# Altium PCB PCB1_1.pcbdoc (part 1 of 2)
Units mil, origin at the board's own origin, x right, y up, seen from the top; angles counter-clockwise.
Board outline 2576.88 x 4443.16 mil, 6 copper layers (Top Layer, Inner1, Inner2, Inner3, Inner4, Bottom Layer); 86 components, 97 nets, 400 pads, 188 vias.
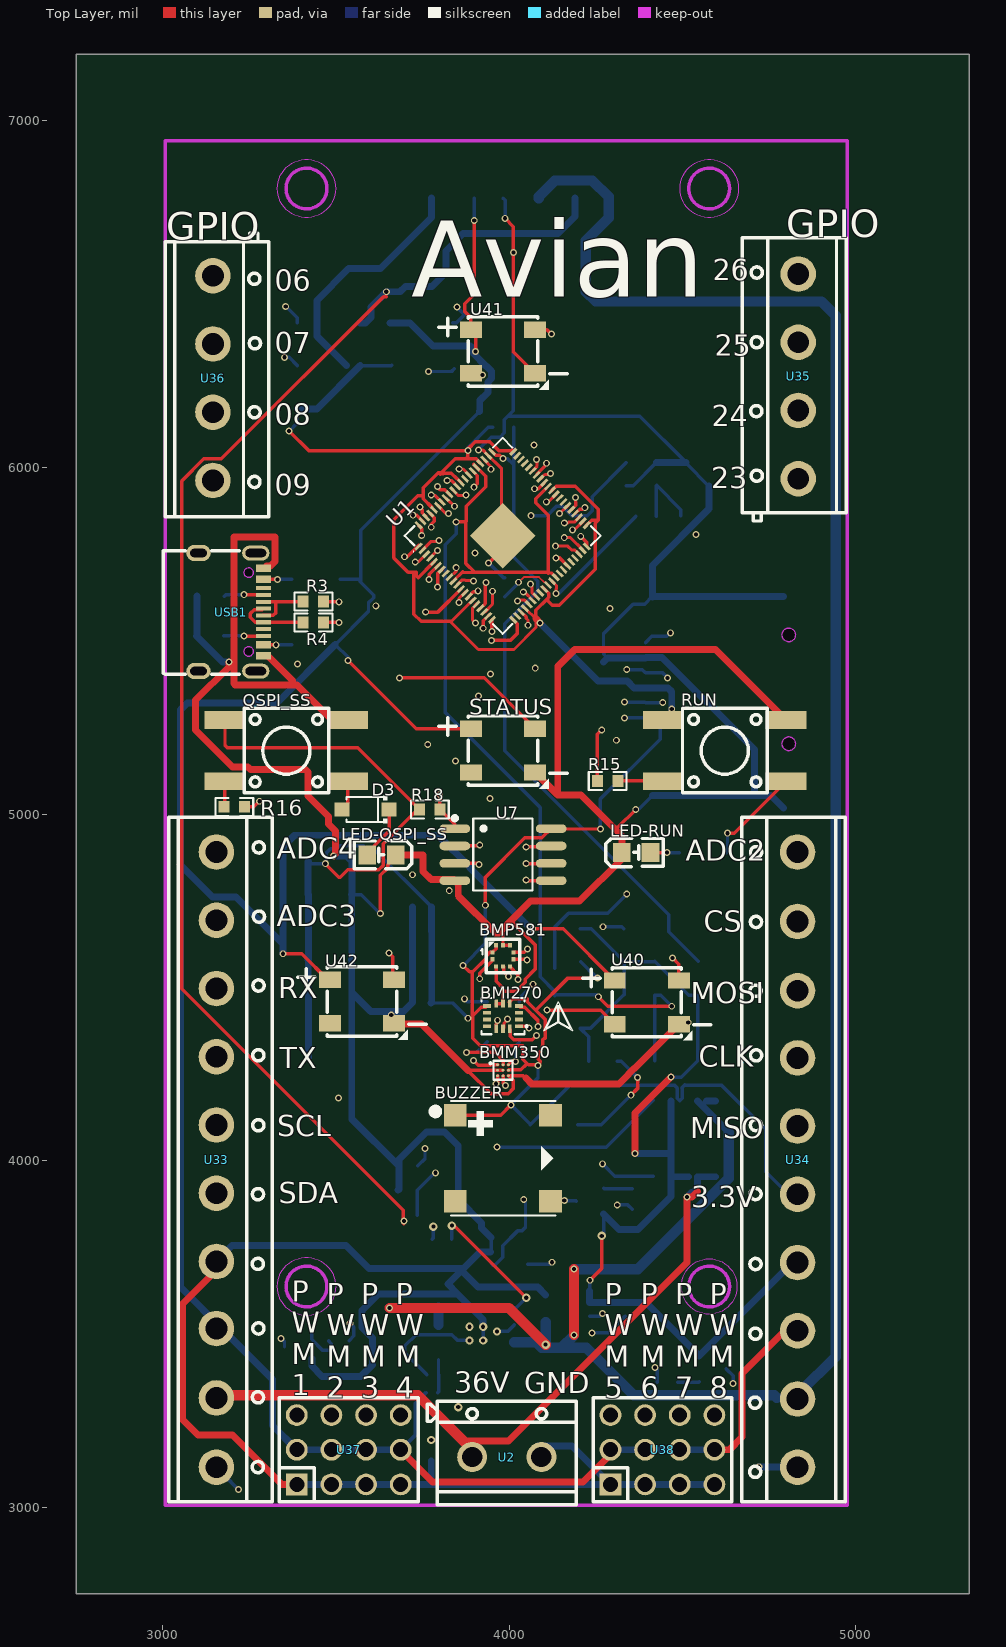
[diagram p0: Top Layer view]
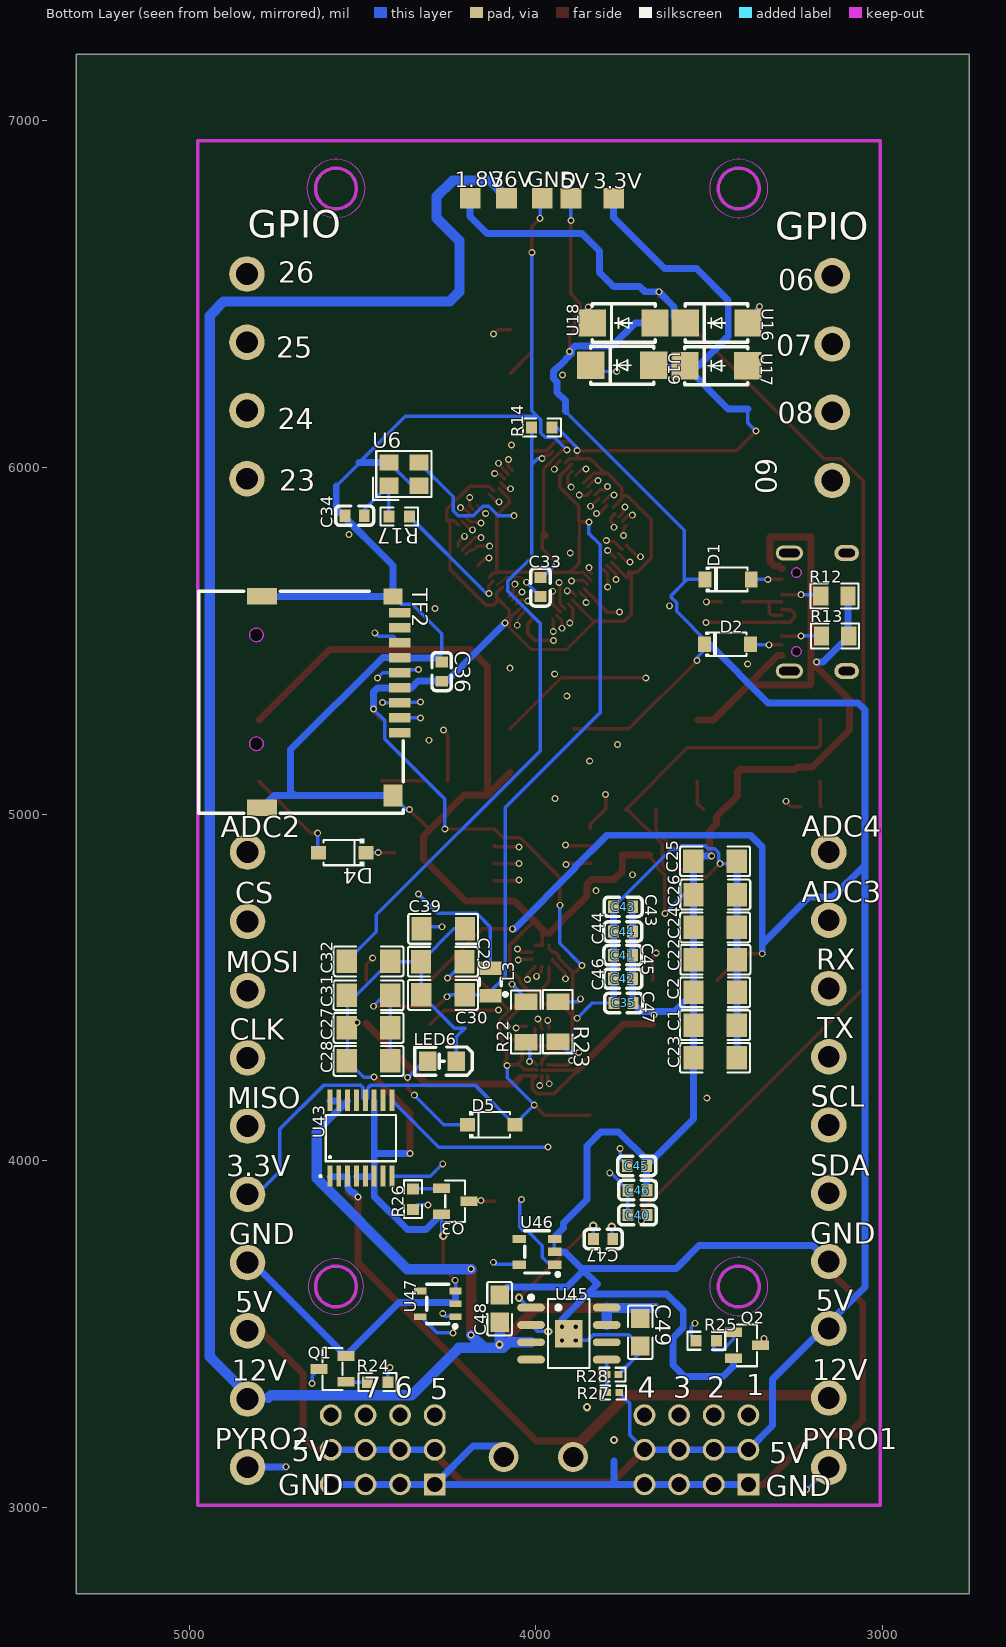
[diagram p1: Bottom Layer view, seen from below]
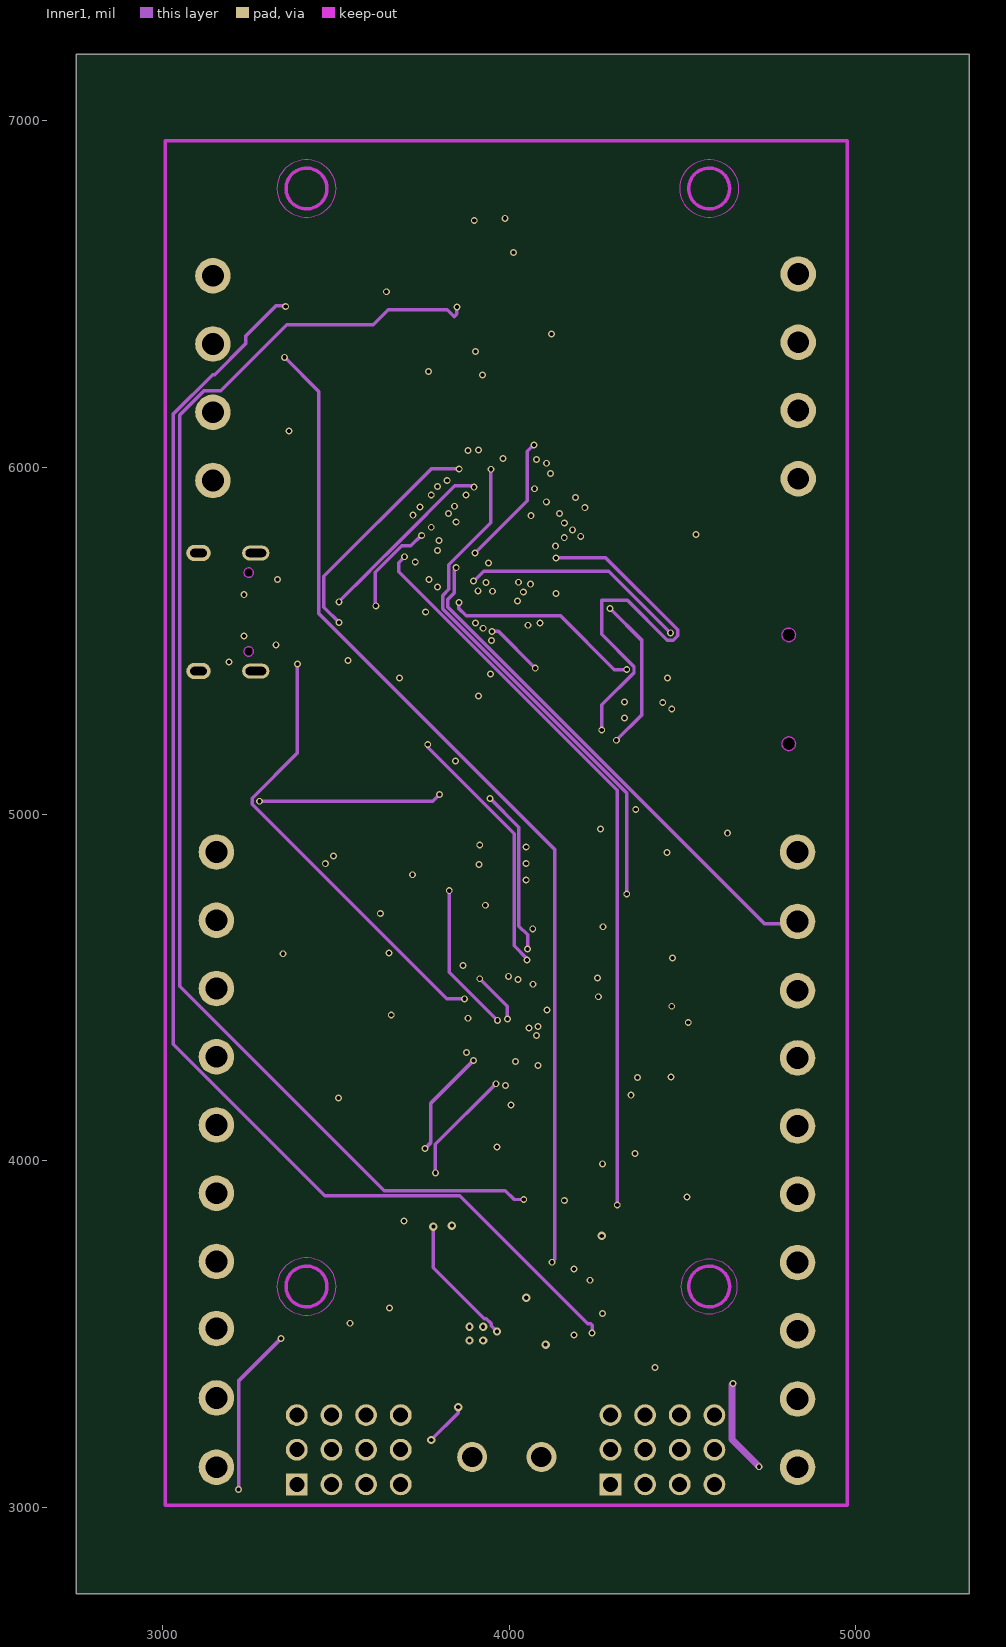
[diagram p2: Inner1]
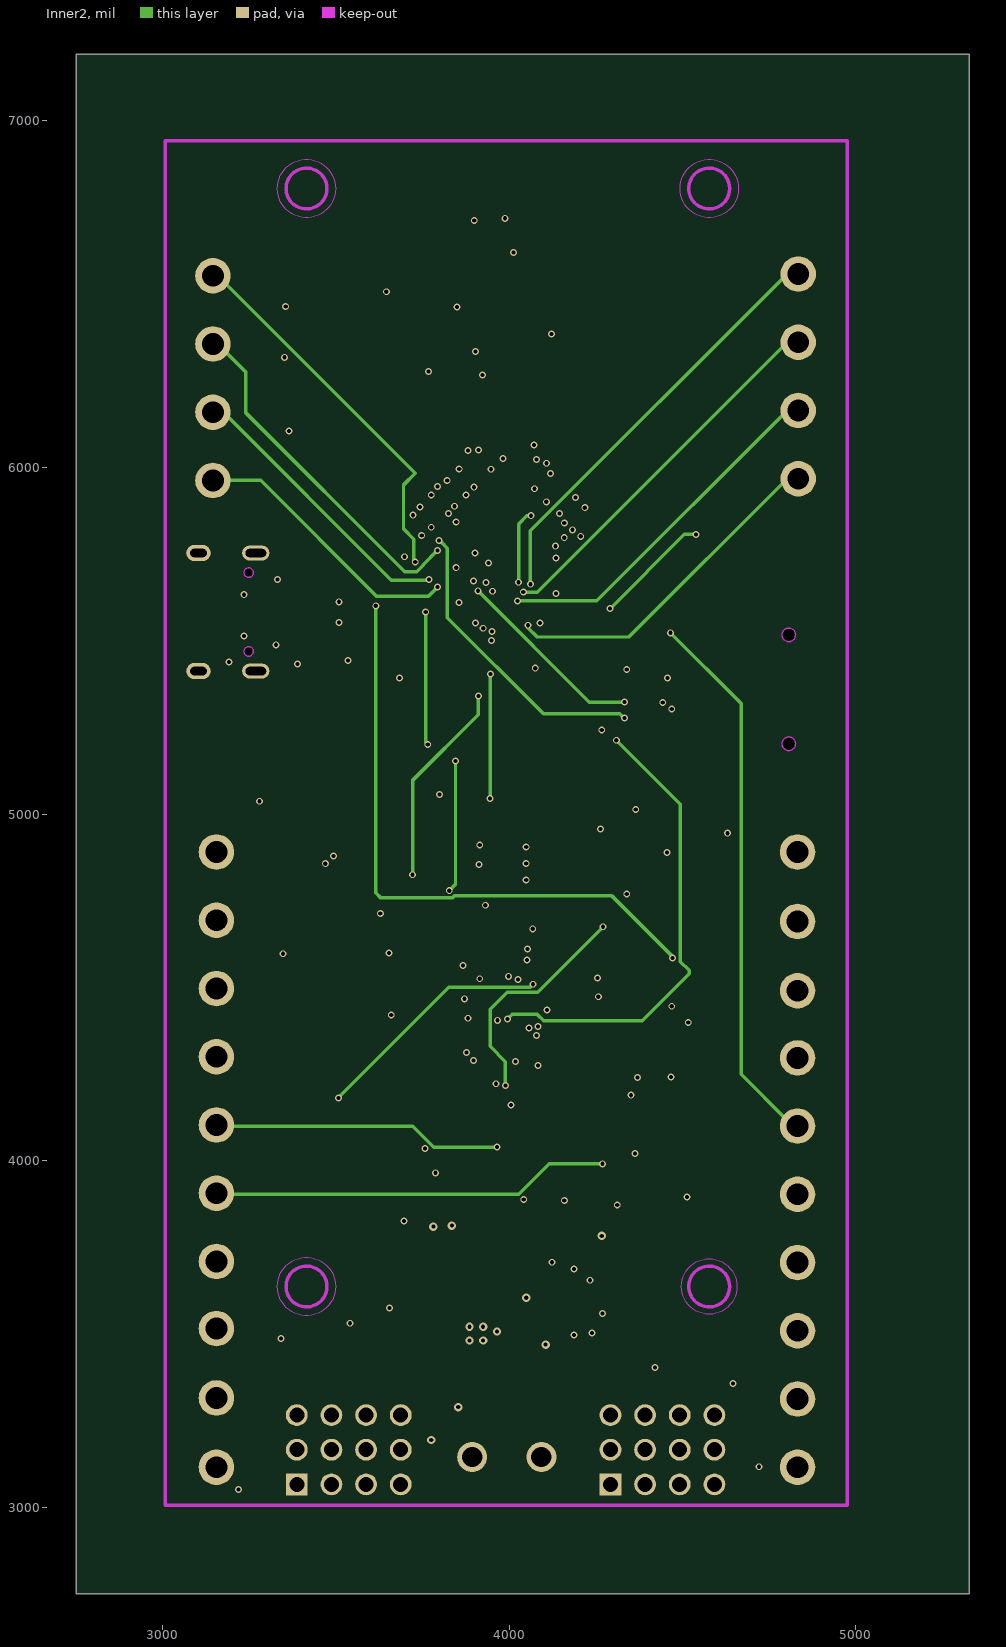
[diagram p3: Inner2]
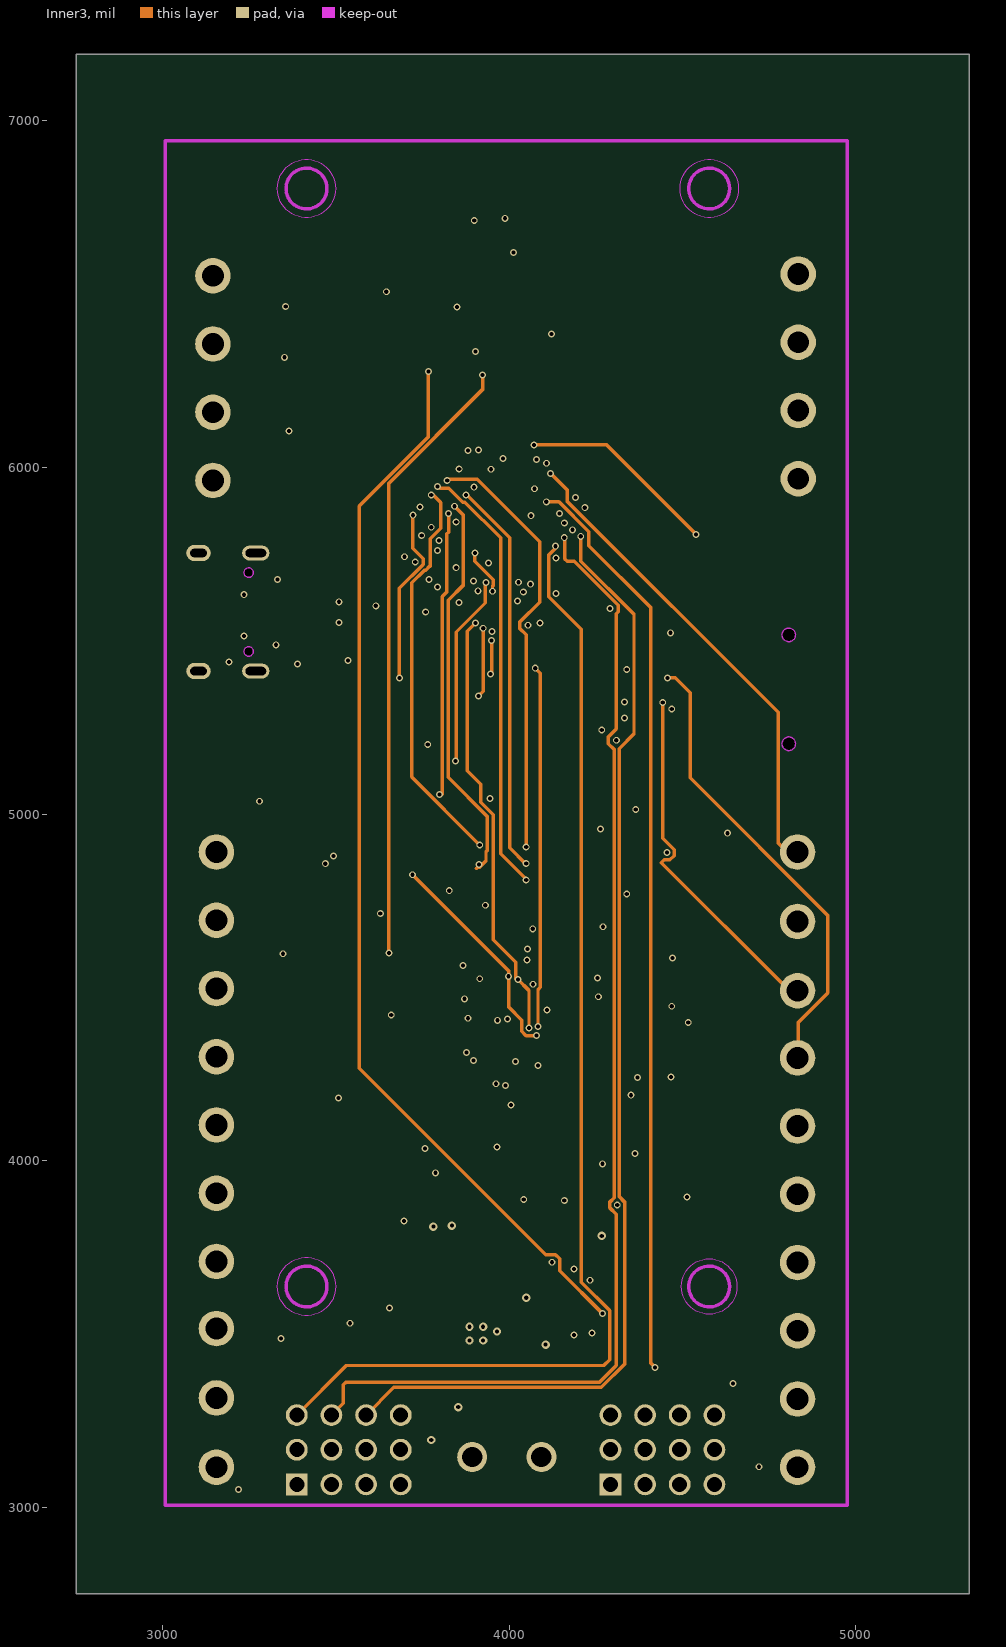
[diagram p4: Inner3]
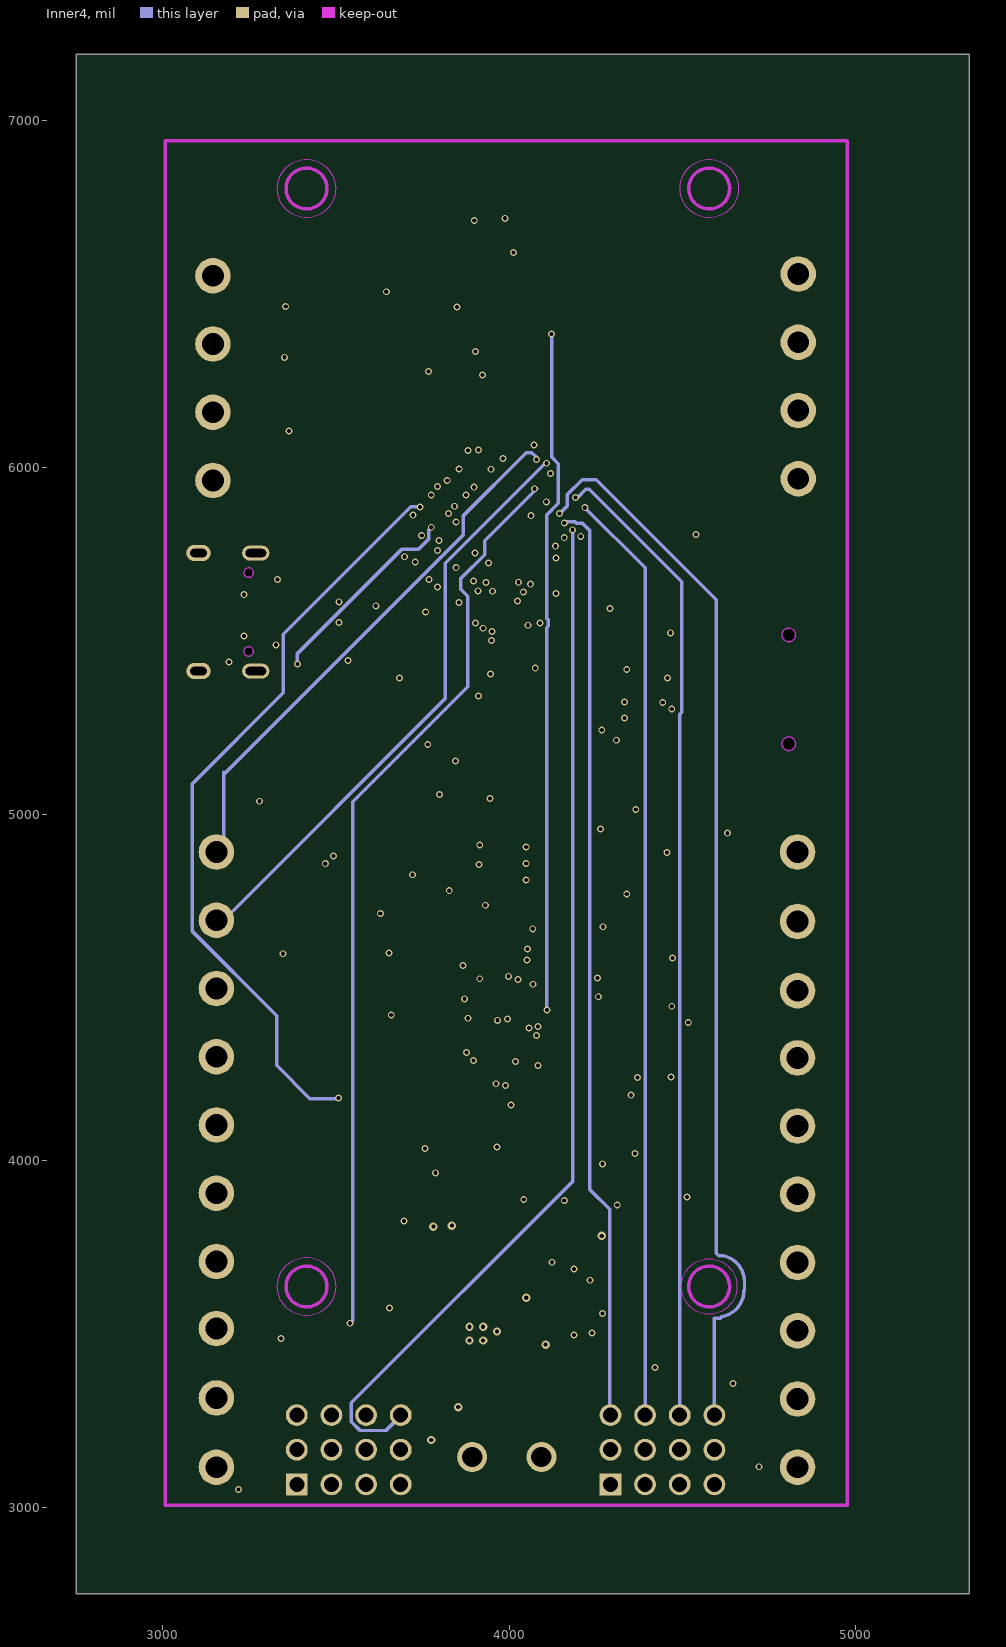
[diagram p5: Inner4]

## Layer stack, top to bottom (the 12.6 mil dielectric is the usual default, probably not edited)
Top Layer: signal copper (thickness not stored)
Dielectric: dielectric 12.6, FR-4, Dk 4.8
Inner1: signal copper (thickness not stored)
Dielectric: dielectric 12.6, FR-4, Dk 4.8
Inner2: signal copper (thickness not stored)
Dielectric: dielectric 12.6, FR-4, Dk 4.8
Inner3: signal copper (thickness not stored)
Dielectric: dielectric 12.6, FR-4, Dk 4.8
Inner4: signal copper (thickness not stored)
Dielectric: dielectric 12.6, FR-4, Dk 4.8
Bottom Layer: signal copper (thickness not stored)

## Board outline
5326.88,2750 2750,2750 2750,7193.16 5326.88,7193.16

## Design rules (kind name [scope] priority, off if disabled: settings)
BoardOutlineClearance copperThickness1oz [All] p0: genericclearance=10 ignorepadtopadclearanceinfootprint=FALSE except(0: Arc-SplitContinuation Track-SplitContinuation SMDPad-SplitContinuation THPad-SplitContinuation Via-SplitContinuation Fill-SplitContinuation Poly-SplitContinuation Region-SplitContinuation Text-SplitContinuation; 6: Track-CutoutEdge SMDPad-CutoutEdge THPad-CutoutEdge Via-CutoutEdge Region-CutoutEdge; 11.8: Track-OutlineEdge SMDPad-OutlineEdge THPad-OutlineEdge Via-OutlineEdge Fill-OutlineEdge Region-OutlineEdge Poly-OutlineEdge Text-OutlineEdge Fill-CutoutEdge)
BoardOutlineClearance copperThickness2oz [All] p0: genericclearance=10 ignorepadtopadclearanceinfootprint=FALSE except(0: Arc-SplitContinuation Track-SplitContinuation SMDPad-SplitContinuation THPad-SplitContinuation Via-SplitContinuation Fill-SplitContinuation Poly-SplitContinuation Region-SplitContinuation Text-SplitContinuation; 6: Track-CutoutEdge SMDPad-CutoutEdge THPad-CutoutEdge Via-CutoutEdge Region-CutoutEdge; 11.8: Track-OutlineEdge SMDPad-OutlineEdge THPad-OutlineEdge Via-OutlineEdge Fill-OutlineEdge Region-OutlineEdge Poly-OutlineEdge Text-OutlineEdge Fill-CutoutEdge)
Clearance copperThickness1oz [(InNet('GND') OR InNet('+5V') OR InNet('RPD-') OR InNet('RPD+') OR InNet('3.3V') OR InNet('1.1V') OR InNet('1.8V') OR InNet('XIN') OR InNet('QSPI_SS') OR InNet('XOUT') OR InNet('QSPI_SD3') OR InNet('QSPI_SCLK') OR InNet('QSPI_SDO') OR InNet('QSPI_SD2') OR InNet('QSPI_SD1') OR InNet('SDCS') OR InNet('MISO') OR InNet('CLK') OR InNet('MOSI') OR InNet('$5N1577') OR InNet('$5N4916') OR InNet('$5N4199') OR InNet('$5N4153') OR InNet('$5N4367') OR InNet('$5N1500') OR InNet('$5N714') OR InNet('$5N753') OR InNet('$5N865') OR InNet('$5N3555') OR InNet('$3N4271') OR InNet('$3N4443') OR InNet('$3N4153') OR InNet('$3N4404') OR InNet('GPIO1') OR InNet('GPIO0') OR InNet('GPIO16') OR InNet('GPIO17') OR InNet('GPIO18') OR InNet('GPIO19') OR InNet('GPIO20') OR InNet('$5N10100') OR InNet('$5N10092') OR InNet('GPIO13') OR InNet('$3N5055') OR InNet('GPIO21') OR InNet('ADC0') OR InNet('ADC1') OR InNet('$5N12933') OR InNet('$5N12881') OR InNet('PISTA') OR InNet('TX') OR InNet('SCL') OR InNet('SDA') OR InNet('CS') OR InNet('ADC2') OR InNet('VCC') OR InNet('NEOIN') OR InNet('$5N18524') OR InNet('$5N18586') OR InNet('GPIO22') OR InNet('GPIO23') OR InNet('GPIO24') OR InNet('GPIO25') OR InNet('GPIO26') OR InNet('PWM1') OR InNet('PWM2') OR InNet('PWM3') OR InNet('PWM4') OR InNet('PWM5') OR InNet('PWM6') OR InNet('PWM7') OR InNet('PWM8') OR InNet('ADC3') OR InNet('ADC4') OR InNet('GPIO6') OR InNet('GPIO7') OR InNet('GPIO8') OR InNet('GPIO9') OR InNet('$3N22326') OR InNet('$3N22330') OR InNet('BUZ') OR InNet('$5N907') OR InNet('$5N24177') OR InNet('$5N24251') OR InNet('$3N25090') OR InNet('$3N25503') OR InNet('$3N25501') OR InNet('RX') OR InNet('$3N26223') OR InNet('$3N26229') OR InNet('$3N29548') OR InNet('$3N29825') OR InNet('$3N29821') OR InNet('$3N29823') OR InNet('$3N29827') OR InNet('$3N29841') OR InNet('$3N29881'))] p1: gap=7 ignorepadtopadclearanceinfootprint=FALSE except(4: Track-Track; 6: Track-SMDPad SMDPad-SMDPad Track-THPad SMDPad-THPad THPad-THPad Track-Via SMDPad-Via THPad-Via Via-Via SMDPad-Fill THPad-Fill Via-Fill Fill-Fill Track-Region SMDPad-Region THPad-Region Via-Region Region-Region Track-Poly SMDPad-Poly THPad-Poly Via-Poly Fill-Poly Region-Poly Poly-Poly Track-Text SMDPad-Text THPad-Text Via-Text Fill-Text Region-Text Poly-Text Text-Text; 6.9: Track-Hole SMDPad-Hole THPad-Hole Via-Hole Fill-Hole Region-Hole Poly-Hole Text-Hole Sheet-Hole; 11.8: Track-Fill Fill-Region Track-Sheet SMDPad-Sheet THPad-Sheet Via-Sheet Fill-Sheet Region-Sheet Poly-Sheet Text-Sheet)
Clearance copperThickness2oz [All] p1: gap=7 ignorepadtopadclearanceinfootprint=FALSE except(6: Track-SMDPad SMDPad-SMDPad Track-THPad SMDPad-THPad THPad-THPad Track-Via SMDPad-Via THPad-Via Via-Via SMDPad-Fill THPad-Fill Via-Fill Fill-Fill Track-Region SMDPad-Region THPad-Region Via-Region Region-Region Track-Poly SMDPad-Poly THPad-Poly Via-Poly Fill-Poly Region-Poly Poly-Poly Track-Text SMDPad-Text THPad-Text Via-Text Fill-Text Region-Text Poly-Text Text-Text; 6.9: Track-Hole SMDPad-Hole THPad-Hole Via-Hole Fill-Hole Region-Hole Poly-Hole Text-Hole Sheet-Hole; 8: Track-Track; 11.8: Track-Fill Fill-Region Track-Sheet SMDPad-Sheet THPad-Sheet Via-Sheet Fill-Sheet Region-Sheet Poly-Sheet Text-Sheet)
DiffPairsRouting differentialPair [All] p1: maxuncoupledlength=10 minlimit=6 maxlimit=6 mostfreqgap=6 toplayer_minwidth=5 toplayer_prefwidth=10 toplayer_maxwidth=100 bottomlayer_minwidth=5 bottomlayer_prefwidth=10 bottomlayer_maxwidth=100 midlayer1_minwidth=5 midlayer1_prefwidth=10 midlayer1_maxwidth=100 midlayer2_minwidth=5 midlayer2_prefwidth=10 midlayer2_maxwidth=100 midlayer3_minwidth=5 midlayer3_prefwidth=10 midlayer3_maxwidth=100 midlayer4_minwidth=5 midlayer4_prefwidth=10 midlayer4_maxwidth=100
PasteMaskExpansion pasteMaskExpansion [All] p1: expansion=0
PlaneConnect innerPlane [All] p1: planeconnectstyle=Relief reliefexpansion=20 reliefentries=4 reliefconductorwidth=10 reliefairgap=10
PolygonConnect copperRegion [All] p1: connectstyle=Relief reliefentries=4 reliefconductorwidth=10 polygonreliefangle="90 Angle" airgapwidth=10
RoutingVias viaSize [All] p1: viastyle="Through Hole" holewidth=12.0078 minholewidth=11.811 maxholewidth=248.0314 width=24.0158 minwidth=19.685 maxwidth=393.7008
SolderMaskExpansion solderMaskExpansion [All] p1: useseparateexpansions=TRUE expansion=2 expansionbottom=2
Width copperThickness1oz [All] p1: maxlimit=100 minlimit=5 preferedwidth=10
Width copperThickness2oz [All] p1: maxlimit=100 minlimit=8 preferedwidth=10

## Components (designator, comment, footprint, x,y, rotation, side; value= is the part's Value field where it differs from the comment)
BMI270 "BMI270" LGA-14_L3.0-W2.5-P0.50-BR 3981.88,4417.16 r0 top
BMM350 "BMM350_C17225907" WLCSP-9_L1.3-W1.3-R3-C3-P0.40-TL 3981.88,4261.16 r0 top
BMP581 "BMP581" LGA-10_L2.0-W2.0-P0.50-TL_BMP581 3981.88,4591.16 r0 top
BUZZER "MLT-7525" BUZ-SMD_4P-L7.5-W7.5-P7.59-TL 3981.88,4007.16 r0 top
C1 "CL31A107MQHNNNE" C1206 3482.88,4391.16 r180 bottom
C2 "CL31A107MQHNNNE" C1206 3482.79,4485.96 r180 bottom
C22 "CL31A107MQHNNNE" C1206 3482.33,4579.96 r180 bottom
C23 "CL31A107MQHNNNE" C1206 3482.88,4297.16 r180 bottom
C24 "CL31A107MQHNNNE" C1206 3482.88,4673.16 r180 bottom
C25 "CL31A107MQHNNNE" C1206 3482.96,4863.96 r180 bottom
C26 "CL31A107MQHNNNE" C1206 3482.51,4767.96 r180 bottom
C27 "CL31A107MQHNNNE" C1206 4482.88,4383.16 r180 bottom
C28 "CL31A107MQHNNNE" C1206 4482.88,4287.96 r180 bottom
C29 "CL31B475KBHNNNE" C1206 4268.53,4574.41 r180 bottom
C30 "CL31B475KBHNNNE" C1206 4268.07,4478.41 r180 bottom
C31 "CL31B475KBHNNNE" C1206 4482.88,4477.16 r180 bottom
C32 "CL31B475KBHNNNE" C1206 4482.88,4575.16 r180 bottom
C33 "CL10C150JB8NNNC" C0603 3986.88,5655.16 r270 bottom
C34 "CL10C150JB8NNNC" C0603 4522.88,5861.16 r180 bottom
C35 "CC0603KRX7R9BB104" C0603 3746.88,4455.16 r180 bottom
C36 "CC0603KRX7R9BB104" C0603 4271.86,5411.13 r270 bottom
C39 "CL31B225KBHNNNE" C1206 4267.48,4669.11 r180 bottom
C40 "CC0603KRX7R9BB103" C0603 3706.88,3843.16 r180 bottom
C41 "CC0603KRX7R9BB104" C0603 3748.88,4593.16 r180 bottom
C42 "CC0603KRX7R9BB104" C0603 3748.88,4525.16 r0 bottom
C43 "CC0603KRX7R9BB104" C0603 3748.16,4732.6 r180 bottom
C44 "CC0603KRX7R9BB104" C0603 3748.88,4661.16 r0 bottom
C45 "CC0603KRX7R9BB104" C0603 3708.88,3985.16 r180 bottom
C46 "CC0603KRX7R9BB104" C0603 3706.88,3915.16 r0 bottom
C47 "CL10B104KB8NNNC" C0603 3805.74,3774.09 r0 bottom
C48 "CL21B106KOQNNNE" C0805 4104.88,3573.16 r90 bottom
C49 "CL21B106KOQNNNE" C0805 3698.88,3505.16 r270 bottom
D1 "MM1Z5V6_C85210" SOD-123_L2.8-W1.8-LS3.7-RD 3445.35,5677.21 r180 bottom
D2 "MM1Z5V6_C85210" SOD-123_L2.8-W1.8-LS3.7-RD 3447.35,5490.53 r180 bottom
D3 "1N4148W_C81598" SOD-123F_L2.7-W1.6-LS3.8-RD 3585.16,5013.57 r180 top
D4 "1N4148W_C81598" SOD-123F_L2.7-W1.6-LS3.8-RD 4558.99,4889.08 r0 bottom
D5 "1N4148W_C81598" SOD-123F_L2.7-W1.6-LS3.8-RD 4129.3,4103.99 r180 bottom
L3 "AOTA-B201610S3R3-101-T" IND-SMD_L2.0-W1.6_AOTA-B201610S3R3-101-T 4131.31,4515.61 r270 bottom
LED6 "YLED0805G" LED0805-FD-GREEN 4270.88,4287.16 r180 bottom
LED-QSPI_SS "YLED0805G" LED0805-FD-GREEN 3631.25,4882.49 r0 top
LED-RUN "YLED0805G" LED0805-FD-GREEN 4366.25,4889.77 r180 top
Q1 "AO3400A_C20917" SOT-23-3_L2.9-W1.3-P1.90-LS2.4-BR 4586.88,3399.16 r180 bottom
Q2 "AO3400A_C20917" SOT-23-3_L2.9-W1.3-P1.90-LS2.4-BR 3390.88,3467.16 r0 bottom
Q3 "AO3400A_C20917" SOT-23-3_L2.9-W1.3-P1.90-LS2.4-BR 4232.88,3883.16 r0 bottom
QSPI_SS "KSC441G70SHLFS" KEY--SMD_4P-L6.2-W6.2-P4.50-LS12.0 3356.88,5183.16 r0 top
R3 "0603WAF2613T5E" R0603 3434.88,5613.16 r0 top
R4 "0603WAF2613T5E" R0603 3434.88,5553.16 r0 top
R12 "0805W8F5101T5E" R0805 3138.88,5629.16 r180 bottom
R13 "0805W8F5101T5E" R0805 3136.56,5514.25 r180 bottom
R14 "FRC0603F33R0TS" R0603 3982.72,6115.91 r0 bottom
R15 "RC0603FR-071KL" R0603 4283.91,5095.89 r180 top
R16 "RC0603FR-071KL" R0603 3206.88,5021.16 r0 top
R17 "RC0603FR-071KL" R0603 4394.34,5858.9 r0 bottom
R18 "RC0603FR-0710KL" R0603 3770.88,5013.16 r180 top
R22 "RMC12064.7K1%N" R1206 4028.95,4399.86 r270 bottom
R23 "RMC12064.7K1%N" R1206 3936.54,4401.16 r270 bottom
R24 "0603WAF1002T5E" R0603 4456.88,3361.16 r0 bottom
R25 "0603WAF1002T5E" R0603 3508.19,3480.64 r180 bottom
R26 "0603WAF1002T5E" R0603 4354.88,3889.16 r90 bottom
R27 "RMC040244.2K1%N" R0402 3776.88,3331.16 r180 bottom
R28 "RMC04026.04K1%N" R0402 3778.88,3383.16 r180 bottom
RUN "KSC441G70SHLFS" KEY--SMD_4P-L6.2-W6.2-P4.50-LS12.0 4621.88,5183.16 r0 top
STATUS "WS2812" LED-SMD_4P-L5.0-W5.0-TL-A 3981.88,5183.16 r0 top
TF2 "TF-CARD H1.8" TF-SMD_TF-CARD-H1.8 4591.88,5323.16 r270 bottom
U1 "RP2350B_C42415655" QFN-80_L10.0-W10.0-P0.40-TL-EP3.4 3980.88,5803.16 r45 top
U2 "JL301-50002U04" CONN-TH_JL301-50002U01 3992.88,3145.16 r0 top
U6 "ABM8-272-T3_C20625731" CRYSTAL-SMD_4P-L3.2-W2.5-BL 4380.88,5981.16 r180 bottom
U7 "W25Q128JVSIQ" SOIC-8_L5.3-W5.3-P1.27-LS8.0-BL 3981.88,4883.16 r270 top
U16 "CDBA140SL-HF" DO-214AC_L4.3-W2.7-LS5.3-RD 3478.88,6417.16 r180 bottom
U17 "CDBA140SL-HF" DO-214AC_L4.3-W2.7-LS5.3-RD 3479.46,6293.87 r180 bottom
U18 "CDBA140SL-HF" DO-214AC_L4.3-W2.7-LS5.3-RD 3746.88,6417.16 r180 bottom
U19 "CDBA140SL-HF" DO-214AC_L4.3-W2.7-LS5.3-RD 3750.88,6295.16 r180 bottom
U33 "JL301-50010U02" CONN-TH_10P-P5.00_JL301-50010U02 3154.88,4003.16 r90 top
U34 "JL301-50010U02" CONN-TH_10P-P5.00_JL301-50010U02 4831.88,4003.16 r270 top
U35 "JL301-50004U02" CONN-TH_4P-P5.00_JL301-50004U02 4833.88,6263.16 r270 top
U36 "JL301-50004U02" CONN-TH_4P-P5.00_JL301-50004U02 3144.88,6258.16 r90 top
U37 "HX PZ2.54-3x4P ZZ" HDR-TH_12P-P2.54-V-M-R3-C4-S2.54 3536.88,3166.16 r0 top
U38 "HX PZ2.54-3x4P ZZ" HDR-TH_12P-P2.54-V-M-R3-C4-S2.54 4441.88,3166.16 r0 top
U40 "WS2812" LED-SMD_4P-L5.0-W5.0-TL-A 4396.88,4457.16 r0 top
U41 "WS2812" LED-SMD_4P-L5.0-W5.0-TL-A 3981.88,6335.16 r0 top
U42 "WS2812" LED-SMD_4P-L5.0-W5.0-TL-A 3574.88,4459.16 r0 top
U43 "INA260AIPWR" TSSOP-16_L5.0-W4.4-P0.65-LS6.4-BL-1 4504.88,4065.16 r180 bottom
U45 "SY8205FCC" SOIC-8_L5.0-W4.0-P1.27-LS6.0-BL-EP2.0 3904.88,3501.16 r270 bottom
U46 "AP2112K-3.3TRG1(MS)" SOT-23-5_L2.9-W1.6-P0.95-LS2.7-BR 3996.88,3737.16 r180 bottom
U47 "AP2112K-1.8TRG1" SOT-25_L3.0-W1.6-P0.95-LS2.8-BL 4282.88,3587.16 r90 bottom
USB1 "TYPE-C 16PIN 2MD(073)" USB-C-SMD_TYPE-C-6PIN-2MD-073 3196.88,5583.16 r270 top

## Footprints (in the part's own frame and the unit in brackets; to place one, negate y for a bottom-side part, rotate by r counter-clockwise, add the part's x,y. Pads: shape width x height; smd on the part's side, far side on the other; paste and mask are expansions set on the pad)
BUZ-SMD_4P-L7.5-W7.5-P7.59-TL [mm]
  rect 1.681x1.68 smd: 1(-3.497,3.15) 2(-3.497,-3.15) 3(3.497,-3.15) 4(3.497,3.15)
  silkscreen extent -5.2,-4.19 3.84,4.19
C0603 [mm]
  rect 0.8x0.9 smd: 1(-0.7,0) 2(0.7,0)
  silkscreen extent -1.39,-0.71 1.39,0.71
C0805 [mm]
  rect 1.41x1.35 smd: 1(-1,0) 2(1,0)
  silkscreen extent -1.96,-0.9 1.96,0.9
C1206 [mm]
  rect 1.485x1.728 smd: 1(-1.593,0) 2(1.593,0)
  silkscreen extent -2.56,-1.09 2.56,1.09
CONN-TH_4P-P5.00_JL301-50004U02 [mm]
  round 2.6 hole 1.6: 1(-7.5,0) 2(-2.5,0) 3(2.5,0) 4(7.5,0)
  silkscreen extent -10.16,-4.1 10.6,3.5
CONN-TH_10P-P5.00_JL301-50010U02 [mm]
  round 2.6 hole 1.6: 1(-22.54,0) 2(-17.46,0) 3(-12.38,0) 4(-7.46,0) 5(-2.46,0) 6(2.54,0) 7(7.54,0) 8(12.54,0) 9(17.54,0) 10(22.54,0)
  silkscreen extent -25.08,-4.1 25.08,3.5
CONN-TH_JL301-50002U01 [mm]
  round 2.2 hole 1.5: 1(-2.54,0) 2(2.54,0)
  silkscreen extent -5.84,-3.5 5.08,4.1
CRYSTAL-SMD_4P-L3.2-W2.5-BL [mm]
  rect 1.4x1.2 smd: 1(-1.1,-0.85) 2(1.1,-0.85) 3(1.1,0.85) 4(-1.1,0.85)
  silkscreen extent -2.26,-1.91 2.03,1.68
DO-214AC_L4.3-W2.7-LS5.3-RD [mm]
  rect 2x2 smd: 1(-2.3,0) 2(2.3,0)
  silkscreen extent -2.3,-1.4 2.3,1.4
HDR-TH_12P-P2.54-V-M-R3-C4-S2.54 [mm]
  rect 1.6x1.6 hole 1.1: 1(-3.81,-2.54)
  round 1.6 hole 1.1: 2(-3.81,0) 3(-3.81,2.54) 4(-1.27,-2.54) 5(-1.27,0) 6(-1.27,2.54) 7(1.27,-2.54) 8(1.27,0) 9(1.27,2.54) 10(3.81,-2.54) 11(3.81,0) 12(3.81,2.54)
  silkscreen extent -5.08,-3.81 5.08,3.81
IND-SMD_L2.0-W1.6_AOTA-B201610S3R3-101-T [mm]
  rect 1x1.6 smd: 1(-1,0) 2(1,0)
  silkscreen extent -0.27,-0.8 1.03,1.23
KEY--SMD_4P-L6.2-W6.2-P4.50-LS12.0 [mm]
  rect 3x1.3 smd: 1(-4.5,2.25) 2(4.5,2.25) 3(-4.5,-2.25) 4(4.5,-2.25)
  silkscreen extent -3.1,-3.1 3.1,3.1
LED0805-FD-GREEN [mil]
  rect 51.2x55.1 smd: 1(-41.35,0) 2(41.35,0)
  silkscreen extent -78,-40 88,41
LED-SMD_4P-L5.0-W5.0-TL-A [mm]
  rect 1.6x1.2 smd: 1(-2.35,1.6) 2(-2.35,-1.6) 3(2.35,-1.6) 4(2.35,1.6)
  silkscreen extent -4.7,-2.79 4.7,2.54
LGA-10_L2.0-W2.0-P0.50-TL_BMP581 [mm]
  rect 0.3x0.3 smd: 1(-0.78,0.25) 2(-0.78,-0.25) 3(-0.5,-0.78) 4(0,-0.78) 5(0.5,-0.78) 6(0.78,-0.25) 7(0.78,0.25) 8(0.5,0.78) 9(0,0.78) 10(-0.5,0.78)
  silkscreen extent -1.6,-1.23 1.23,1.23
LGA-14_L3.0-W2.5-P0.50-BR [mm]
  rect 0.6x0.27 smd: 1(1.17,-0.75) 2(1.17,-0.25) 3(1.17,0.25) 4(1.17,0.75) 8(-1.17,0.75) 9(-1.17,0.25) 10(-1.17,-0.25) 11(-1.17,-0.75)
  rect 0.27x0.6 smd: 5(0.5,0.92) 6(0,0.92) 7(-0.5,0.92) 12(-0.5,-0.92) 13(0,-0.92) 14(0.5,-0.92)
  silkscreen extent -1.58,-1.33 1.8,1.33
QFN-80_L10.0-W10.0-P0.40-TL-EP3.4 [mm]
  rect 0.665x0.22 smd: 1(-4.908,3.8) 2(-4.908,3.4) 3(-4.908,3) 4(-4.908,2.6) 5(-4.908,2.2) 6(-4.908,1.8) 7(-4.908,1.4) 8(-4.908,1) 9(-4.908,0.6) 10(-4.908,0.2) 11(-4.908,-0.2) 12(-4.908,-0.6) 13(-4.908,-1) 14(-4.908,-1.4) 15(-4.908,-1.8) 16(-4.908,-2.2) 17(-4.908,-2.6) 18(-4.908,-3) 19(-4.908,-3.4) 20(-4.908,-3.8) 41(4.908,-3.8) 42(4.908,-3.4) 43(4.908,-3) 44(4.908,-2.6) 45(4.908,-2.2) 46(4.908,-1.8) 47(4.908,-1.4) 48(4.908,-1) 49(4.908,-0.6) 50(4.908,-0.2) 51(4.908,0.2) 52(4.908,0.6) 53(4.908,1) 54(4.908,1.4) 55(4.908,1.8) 56(4.908,2.2) 57(4.908,2.6) 58(4.908,3) 59(4.908,3.4) 60(4.908,3.8)
  rect 0.22x0.665 smd: 21(-3.8,-4.908) 22(-3.4,-4.908) 23(-3,-4.908) 24(-2.6,-4.908) 25(-2.2,-4.908) 26(-1.8,-4.908) 27(-1.4,-4.908) 28(-1,-4.908) 29(-0.6,-4.908) 30(-0.2,-4.908) 31(0.2,-4.908) 32(0.6,-4.908) 33(1,-4.908) 34(1.4,-4.908) 35(1.8,-4.908) 36(2.2,-4.908) 37(2.6,-4.908) 38(3,-4.908) 39(3.4,-4.908) 40(3.8,-4.908) 61(3.8,4.908) 62(3.4,4.908) 63(3,4.908) 64(2.6,4.908) 65(2.2,4.908) 66(1.8,4.908) 67(1.4,4.908) 68(1,4.908) 69(0.6,4.908) 70(0.2,4.908) 71(-0.2,4.908) 72(-0.6,4.908) 73(-1,4.908) 74(-1.4,4.908) 75(-1.8,4.908) 76(-2.2,4.908) 77(-2.6,4.908) 78(-3,4.908) 79(-3.4,4.908) 80(-3.8,4.908)
  rect 3.4x3.4 smd: 81(0,0)
  silkscreen extent -5.47,-5.08 5.08,5.08
R0402 [mm]
  rect 0.566x0.54 smd: 1(-0.433,0) 2(0.433,0)
  silkscreen extent -0.94,-0.5 0.94,0.5
R0603 [mil]
  rect 31.75x34.02 smd: 1(-29.66,0) 2(29.66,0)
  silkscreen extent -55,-26 55,26
R0805 [mm]
  rect 1.133x1.377 smd: 1(-1,0) 2(1,0)
  silkscreen extent -1.76,-0.92 1.76,0.92
R1206 [mil]
  rect 47.54x66.97 smd: 1(-58.22,0) 2(58.22,0)
  silkscreen extent -91,-42 91,42
SOD-123_L2.8-W1.8-LS3.7-RD [mm]
  rect 0.95x1.15 smd: 1(-1.692,0) 2(1.692,0)
  silkscreen extent -1.58,-0.87 1.41,0.87
SOD-123F_L2.7-W1.6-LS3.8-RD [mm]
  rect 1.1x1 smd: 1(-1.735,0) 2(1.735,0)
  silkscreen extent -1.6,-1 1.38,1
SOIC-8_L5.0-W4.0-P1.27-LS6.0-BL-EP2.0 [mm]
  oval 0.574x2.038 smd: 1(-1.905,-2.769) 2(-0.635,-2.769) 3(0.635,-2.769) 4(1.905,-2.769) 5(1.905,2.769) 6(0.635,2.769) 7(-0.635,2.769) 8(-1.905,2.769)
  rect 2x2 smd: 9(0,0)
  silkscreen extent -2.79,-2.92 2.53,1.52
SOIC-8_L5.3-W5.3-P1.27-LS8.0-BL [mm]
  oval 0.63x2.25 smd: 1(-1.905,-3.53) 2(-0.635,-3.53) 3(0.635,-3.53) 4(1.905,-3.53) 5(1.905,3.53) 6(0.635,3.53) 7(-0.635,3.53) 8(-1.905,3.53)
  silkscreen extent -2.82,-3.68 2.64,2.18
SOT-23-3_L2.9-W1.3-P1.90-LS2.4-BR [mm]
  rect 1.25x0.7 smd: 1(1,-0.95) 2(1,0.95) 3(-1,0)
  silkscreen extent -0.73,-1.53 0.73,1.53
SOT-23-5_L2.9-W1.6-P0.95-LS2.7-BR [mm]
  rect 1x0.6 smd: 1(1.3,-0.95) 2(1.3,0) 3(1.3,0.95) 4(-1.3,0.95) 5(-1.3,-0.95)
  silkscreen extent -0.9,-1.78 1.65,1.55
SOT-25_L3.0-W1.6-P0.95-LS2.8-BL [mm]
  rect 0.5x0.9 smd: 1(-0.95,-1.3) 2(0,-1.3) 3(0.95,-1.3) 4(0.95,1.3) 5(-0.95,1.3)
  silkscreen extent -1.78,-1.4 1.45,0.8
TF-SMD_TF-CARD-H1.8 [mm]
  rect 0.7x1.6 smd: 1(2.25,5.05) 2(1.15,5.05) 3(0.05,5.05) 4(-1.05,5.05) 5(-2.15,5.05) 6(-3.25,5.05) 7(-4.35,5.05) 8(-5.45,5.05) 9(-6.55,5.05)
  rect 1.2x1.4 smd: 10(-7.747,4.55)
  rect 1.2x2.2 smd: 11(-7.75,-5.05) 12(7.75,-5.05)
  rect 1.6x1.4 smd: 13(6.85,4.55)
  Board Outline Layer circle w0.005: c3.05,-5.45 r0.5
  Board Outline Layer circle w0.005: c-4.93,-5.45 r0.5
  Board Outline Layer region: 3.05,-5.95 3.267,-5.9 3.441,-5.762 3.537,-5.561 3.537,-5.339 3.441,-5.138 3.267,-4.999 3.05,-4.95 3.05,-4.95 2.833,-4.999 2.659,-5.138 2.563,-5.339 2.563,-5.561 2.659,-5.762 2.833,-5.9 3.05,-5.95
  Board Outline Layer region: -4.93,-5.95 -4.713,-5.9 -4.539,-5.762 -4.443,-5.561 -4.443,-5.339 -4.539,-5.138 -4.713,-4.999 -4.93,-4.95 -4.93,-4.95 -5.147,-4.999 -5.321,-5.138 -5.418,-5.339 -5.418,-5.561 -5.321,-5.762 -5.147,-5.9 -4.93,-5.95
  Multi-Layer board cut-out: 3.05,-5.95 3.267,-5.9 3.441,-5.762 3.537,-5.561 3.537,-5.339 3.441,-5.138 3.267,-4.999 3.05,-4.95 3.05,-4.95 2.833,-4.999 2.659,-5.138 2.563,-5.339 2.563,-5.561 2.659,-5.762 2.833,-5.9 3.05,-5.95
  Multi-Layer board cut-out: -4.93,-5.95 -4.713,-5.9 -4.539,-5.762 -4.443,-5.561 -4.443,-5.339 -4.539,-5.138 -4.713,-4.999 -4.93,-4.95 -4.93,-4.95 -5.147,-4.999 -5.321,-5.138 -5.418,-5.339 -5.418,-5.561 -5.321,-5.762 -5.147,-5.9 -4.93,-5.95
  silkscreen extent -8.13,-9.68 8.13,5.3
TSSOP-16_L5.0-W4.4-P0.65-LS6.4-BL-1 [mm]
  rect 0.364x1.56 smd: 1(-2.275,-2.78) 2(-1.625,-2.78) 3(-0.975,-2.78) 4(-0.325,-2.78) 5(0.325,-2.78) 6(0.975,-2.78) 7(1.625,-2.78) 8(2.275,-2.78) 9(2.275,2.78) 10(1.625,2.78) 11(0.975,2.78) 12(0.325,2.78) 13(-0.325,2.78) 14(-0.975,2.78) 15(-1.625,2.78) 16(-2.275,2.78)
  silkscreen extent -3.03,-2.85 2.58,1.7
USB-C-SMD_TYPE-C-6PIN-2MD-073 [mm]
  rect 0.55x1.1 smd: 1(-3.2,2.375) 2(-2.4,2.375) 11(2.4,2.375) 12(3.2,2.375)
  rect 0.3x1.1 smd: 3(-1.75,2.375) 4(-1.25,2.375) 5(-0.75,2.375) 6(-0.25,2.375) 7(0.25,2.375) 8(0.75,2.375) 9(1.25,2.375) 10(1.75,2.375)
  oval 1.2x1.8 hole 0.6 slot 1.2 at 90 deg: 13(-4.325,-2.375) 14(4.325,-2.375)
  oval 1.1x2 hole 0.6 slot 1.5 at 90 deg: 13(-4.325,1.825) 14(4.325,1.825)
  Board Outline Layer circle w0.005: c-2.89,1.305 r0.35
  Board Outline Layer circle w0.005: c2.89,1.305 r0.35
  Board Outline Layer region: -2.89,1.655 -2.738,1.62 -2.616,1.523 -2.549,1.383 -2.549,1.227 -2.616,1.087 -2.738,0.99 -2.89,0.955 -2.89,0.955 -3.042,0.99 -3.164,1.087 -3.231,1.227 -3.231,1.383 -3.164,1.523 -3.042,1.62 -2.89,1.655
  Board Outline Layer region: 2.89,1.655 3.042,1.62 3.164,1.523 3.231,1.383 3.231,1.227 3.164,1.087 3.042,0.99 2.89,0.955 2.89,0.955 2.738,0.99 2.616,1.087 2.549,1.227 2.549,1.383 2.616,1.523 2.738,1.62 2.89,1.655
  Multi-Layer board cut-out: -2.89,1.655 -2.738,1.62 -2.616,1.523 -2.549,1.383 -2.549,1.227 -2.616,1.087 -2.738,0.99 -2.89,0.955 -2.89,0.955 -3.042,0.99 -3.164,1.087 -3.231,1.227 -3.231,1.383 -3.164,1.523 -3.042,1.62 -2.89,1.655
  Multi-Layer board cut-out: 2.89,1.655 3.042,1.62 3.164,1.523 3.231,1.383 3.231,1.227 3.164,1.087 3.042,0.99 2.89,0.955 2.89,0.955 2.738,0.99 2.616,1.087 2.549,1.227 2.549,1.383 2.616,1.523 2.738,1.62 2.89,1.655
  silkscreen extent -4.5,-4.97 4.57,0.6
WLCSP-9_L1.3-W1.3-R3-C3-P0.40-TL [mm]
  round 0.2 smd: A1(-0.4,0.4) A2(0,0.4) A3(0.4,0.4) B1(-0.4,0) B2(0,0) B3(0.4,0) C1(-0.4,-0.4) C2(0,-0.4) C3(0.4,-0.4)
  silkscreen extent -1,-0.7 0.7,0.7

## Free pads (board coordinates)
  rect 60x60 smd far side: 1(4189.68,6777.16) 2(4084.88,6777.16) 3(3981.88,6777.16) 4(3898.88,6777.16) 5(3775.68,6777.16)

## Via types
v1: diameter 20, hole 12.01, Top Layer to Bottom Layer, 175 vias
v2: diameter 24.02, hole 12.01, Top Layer to Bottom Layer, 8 vias
v3: diameter 24, hole 12, Top Layer to Bottom Layer, 4 vias
v4: diameter 20, hole 12, Top Layer to Bottom Layer, 1 vias

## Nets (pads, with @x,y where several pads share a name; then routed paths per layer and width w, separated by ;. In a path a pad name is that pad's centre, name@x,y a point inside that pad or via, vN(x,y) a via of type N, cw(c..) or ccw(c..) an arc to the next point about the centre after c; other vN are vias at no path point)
1.1V: C27.2 C28.2 C30.2 C31.2 L3.2 U1.10 U1.32 U1.51 U1.65 | length 3084.7
  Top Layer w9: U1.10@3840.3,5674.11 3865.72,5699.52 ; 3865.72,5697.52 3900.52,5697.52 3902.52,5697.52 ; 4112.42,5695.41 4122.95,5695.41 U1.32@4135.11,5683.24
  Top Layer w10: v1(3846.88,5843.16) 3874.06,5843.16 3874.25,5843.35 ; 3874.25,5845.35 3874.25,5843.35 ; U1.65@3897.95,6008.98 3931.88,5975.04 3931.88,5944.59 3876.25,5888.96 3876.25,5845.35 3874.25,5843.35 ; 3900.52,5697.52 3874.88,5723.16 3874.88,5797.98 3874.25,5798.61 3874.25,5843.35 ; 3902.52,5697.52 4110.31,5697.52 4112.42,5695.41 4112.42,5697.41 4112.42,5862.62 4076.88,5898.16 4076.88,5909.91 U1.51@4105.57,5938.59 ; v1(4256.88,4473.16) 4284.38,4445.66 v1(4468.75,4445.66)
  Bottom Layer w10: v1(3846.88,5843.16) 3846.88,5809.48 3814.88,5777.48 3814.88,5293.16 4088.83,5019.22 4088.83,4530.75 4131.31,4488.26 L3.2@4131.31,4476.24 4133.48,4478.41 C30.2@4205.37,4478.41 4251.63,4478.41 v1(4256.88,4473.16) ; C28.2@4420.18,4287.96 C27.2@4420.18,4383.16 C31.2@4420.18,4477.16 4437.25,4477.16 v1(4468.75,4445.66)
1.8V: C40.2 pad.1 U16.1 | length 4073.9
  Top Layer w10: 3645.17,6493.34 3637.17,6493.34 3168.87,6025.05 3118.77,6025.05 3054.96,5961.24 3054.96,4496.7 3694.06,3857.6 3694.06,3820.16 v1@3696.06,3818.16
  Bottom Layer w20: U16.1@3569.43,6417.16 3585.43,6417.16 3600.98,6432.71 3600.98,6463.15 v1(3645.17,6507.34) 3685.17,6507.34 3700.68,6522.85 3776.57,6522.85 3816.88,6563.16 3816.88,6625.16 3866.88,6675.16 4140.88,6675.16 4189.68,6723.95 pad.1@4189.68,6777.16
  other v1: 3696.06,3826.16
3.3V: BMI270.5 BMI270.8 BMM350.B3 BMP581.1 BMP581.10 BUZZER.1 C1.2 C2.2 C22.2 C23.2 C24.2 C25.2 C26.2 C29.2 C35.1 C36.2 C41.1 C42.2 C43.1 C44.2 D5.2 pad.5 QSPI_SS.1 R14.1 R18.2 RUN.1 TF2.4 U1.5 U1.15 U1.24 U1.29 U1.41 U1.50 U1.60 U1.64 U1.69 U1.76 U7.8 U17.1 U19.2 U34.6 U43.12 | length 11009.1
  Top Layer w9: U1.15@3895.38,5618.43 3831.5,5554.55 3910.88,5475.16 4013.7,5475.16 4076.88,5538.34 4076.88,5563.95 ; U1.24@4046.74,5592.16 4076.88,5563.95 ; 4077.88,5563.02 4076.88,5563.95
  Top Layer w10: QSPI_SS.1@3179.72,5271.74 3179.81,5271.65 3179.81,5198.23 3186.88,5191.16 3563.22,5191.16 R18.2@3741.22,5013.16 3734.58,5013.16 3636.01,4914.59 3636.01,4851.95 3623.91,4839.84 3534.56,4839.84 3512.59,4817.87 3508.45,4817.87 v1(3469.27,4857.05) ; v1(3364.88,6105.16) 3420.88,6049.16 v1(3880.88,6049.16) ; U1.76@3777.04,5884.9 3751.88,5910.06 3751.88,5918.16 ; U1.5@3781.46,5726.62 3737.44,5682.6 3731.88,5688.16 3731.88,5698.16 ; 3802.88,5984.62 3803.29,5984.62 ; 3803.29,5982.62 3809.83,5982.62 3811.36,5984.15 3832.76,5984.15 3847.65,5969.26 3848.78,5969.26 U1.69@3861.56,5956.48 ; 3831.5,5556.55 3745.5,5556.55 3724.88,5577.16 3724.88,5691.16 3731.88,5698.16 ; BUZZER.1@3844.19,4131.18 3974.9,4131.18 v1(4004.88,4161.16) ; v1(3866.88,4563.16) 3885.34,4544.71 3894.88,4544.71 ; U1.64@3915.46,6013.73 3904.25,6024.94 3874.45,6024.94 ; v1(3930.88,4737.16) 3930.88,4817.32 4045.11,4931.55 4094.25,4931.55 U7.8@4120.86,4958.16 4121.86,4957.16 v1(4262.88,4957.16) ; BMI270.8@3935.82,4446.7 3932.43,4443.31 3919.46,4443.31 3894.88,4418.73 ; BMP581.10@3962.2,4621.87 3962.2,4612.02 BMP581.1@3951.18,4601 3943.51,4601 3934.29,4591.78 3934.29,4584.11 3894.88,4544.71 ; BMM350.B3@3997.63,4261.16 3998.46,4261.99 4033.71,4261.99 4050.88,4279.16 4050.88,4281.45 ; BMI270.5@3999.56,4457.38 3999.97,4457.38 4009.59,4467 4052.31,4467 4052.31,4459 4076.76,4434.55 ; 4009.12,6049.16 3969.12,6049.16 3944.13,6074.15 3901.36,6074.15 3880.88,6053.68 v1(3880.88,6049.16) ; 4009.12,6051.16 U1.60@4012.71,6047.57 ; 4076.88,5564.02 4076.88,5588.16 4110.87,5622.15 ; v1@4080.88,4275.16 v1@4081.25,4276.8 ; v1(4082.88,4275.16) v1@4081.25,4276.8 ; v1@4087.25,4276.8 4089.47,4286.9 4083.9,4292.47 4083.9,4309.85 4092.88,4318.84 4092.88,4319.16 4096.42,4335.18 4096.42,4349.72 4100.42,4353.72 ; U1.29@4096.49,5654.53 4113.97,5637.06 4113.97,5625.25 4110.87,5622.15 ; 4104.42,4353.72 4104.42,4406.89 4076.76,4434.55 ; U1.50@4121.7,5932.45 4135.63,5946.38 4190.18,5946.38 4256.88,5879.68 4256.88,5848.16 ; U1.41@4222.7,5833.01 4237.85,5848.16 4256.88,5848.16 ; v1(4254.95,4527.16) 4169.37,4527.16 4076.76,4434.55 ; RUN.1@4444.72,5271.74 4468.88,5295.91 v1(4468.88,5303.16) ; 3731.88,5698.16 3707.88,5698.16 3666.88,5739.16 3666.88,5848.99 3736.05,5918.16 3751.88,5918.16 ; 3751.88,5918.16 3751.88,5942.16 3794.88,5985.16 3797.42,5985.16 3801.42,5981.16 3802.88,5982.62 3802.88,5984.22 3803.29,5984.62 ; 3803.29,5984.62 3843.61,6024.94 3874.45,6024.94 ; 3874.45,6024.94 3880.88,6031.38 v1(3880.88,6049.16) ; 3894.88,4418.73 3894.88,4353.16 3915.73,4332.32 4039.08,4332.32 4039.08,4293.25 4050.88,4281.45 ; 3894.88,4418.73 3893.88,4419.74 3893.88,4543.7 3894.88,4544.71 ; 4050.88,4281.45 4055.53,4276.8 v1@4081.25,4276.8 ; 4110.87,5622.15 4110.87,5615.17 4123.88,5602.16 4143.88,5602.16 4247.88,5706.16 4247.88,5839.16 4256.88,5848.16
  Top Layer w20: 4076.88,5564.02 4077.88,5563.02 4088.88,5552.02 v1(4088.88,5551.16)
  Bottom Layer w10: v1(3364.88,6105.16) 3388.33,6128.61 3388.33,6169.16 ; C25.2@3420.26,4863.96 3427.17,4857.05 v1(3469.27,4857.05) 3471.9,4859.68 3471.9,4887.85 3484.19,4900.15 3503.07,4900.15 3511.88,4908.96 3579.44,4908.96 3589.35,4899.05 3609.27,4899.05 C43.1@3775.72,4732.6 ; U17.1@3570.01,6293.87 3659.04,6293.87 U19.2@3660.33,6295.16 ; C35.1@3774.44,4455.16 3836.88,4455.16 v1(3880.88,4411.16) ; v1(3866.88,4563.16) 3930.88,4627.16 v1(3930.88,4737.16) ; v1(3880.88,6049.16) 3880.88,6057.16 3939.63,6115.91 R14.1@3953.06,6115.91 ; v1(4082.88,4275.16) 4082.88,4239.16 v1(4004.88,4161.16) 4061,4105.05 D5.2@4061,4103.99 4174.17,4217.16 4477.35,4217.16 4484.64,4209.87 4484.64,4180.05 4492.08,4172.61 4499.53,4180.06 4499.53,4207.87 ; C29.2@4205.83,4574.41 4253.08,4527.16 v1(4254.95,4527.16) ; v1(4262.88,4957.16) 4262.88,5043.59 4435.55,5216.25 4435.55,5269.83 v1(4468.88,5303.16) ; 4497.53,4209.87 4506.83,4219.16 ; 4508.83,4217.16 4612.88,4217.16 4739.72,4090.33 4739.72,3968.47 U34.6@4801.88,3906.31
  Bottom Layer w20: 3388.33,6169.16 3445.3,6169.16 U17.1@3570.01,6293.87 ; C23.2@3420.18,4297.16 C1.2@3420.18,4391.16 3420.18,4485.86 C2.2@3420.09,4485.96 3420.09,4579.5 C22.2@3419.63,4579.96 3420.18,4580.51 C24.2@3420.18,4673.16 3420.18,4767.58 C26.2@3419.81,4767.96 3419.81,4863.5 C25.2@3420.26,4863.96 ; 3530.01,6293.87 3445.03,6378.86 3445.03,6482.46 3536.8,6574.23 3628.57,6574.23 3775.68,6721.34 pad.5@3775.68,6777.16 ; C35.1@3774.44,4455.16 3776.44,4457.16 C42.2@3776.44,4525.16 C41.1@3776.44,4593.16 C44.2@3776.44,4661.16 3775.72,4661.88 3775.72,4730.6 C43.1@3775.72,4732.6 ; v1(4088.88,5551.16) 4256.47,5383.57 4340.47,5383.57 4359.54,5364.5 TF2.4@4393.07,5364.5 4457.54,5364.5 4468.88,5353.16 v1(4468.88,5303.16)
$3N4153: BMM350.C2 C39.1 | length 755.8
  Top Layer w10: BMM350.C2@3981.88,4245.41 3982.71,4244.58 3982.71,4223.33 v1(3988.88,4217.16)
  Inner2 w10: v1(3988.88,4217.16) 3988.88,4285.86 3944.88,4329.86 3944.88,4437.16 3993.88,4486.15 4081.88,4486.15 v1(4270.88,4675.16)
  Bottom Layer w10: v1(4270.88,4675.16) 4324.12,4675.16 C39.1@4330.18,4669.11
$3N4271: BMM350.C1 C40.1 C46.2 | length 499.6
  Top Layer w10: v1(3961.6,4222.23) 3966.13,4226.76 BMM350.C1@3966.13,4245.41
  Inner1 w10: v1(3786.88,3965.16) 3786.88,4047.51 v1(3961.6,4222.23)
  Bottom Layer w10: C40.1@3734.44,3843.16 C46.2@3734.44,3915.16 3784.44,3965.16 v1(3786.88,3965.16)
$3N4404: BMM350.A3 R22.2 | length 84
  Top Layer w10: BMM350.A3@3997.63,4276.91 4007.26,4286.54 v1(4018.09,4286.54)
  Bottom Layer w10: v1(4018.09,4286.54) 4018.09,4330.79 R22.2@4028.95,4341.64
$3N4443: BMM350.A2 R23.2 | length 200.7
  Top Layer w10: v1(3876.54,4312.75) 3959.16,4312.75 3982.71,4289.19 BMM350.A2@3982.71,4276.91
  Bottom Layer w10: v1(3876.54,4312.75) 3906.35,4312.75 R23.2@3936.54,4342.94
$3N5055: BMM350.A1 C45.1 | length 445.7
  Top Layer w10: v1(3896.88,4289.16) 3910.28,4275.76 3945.23,4275.76 3946.38,4276.91 BMM350.A1@3966.13,4276.91
  Inner1 w10: v1(3756.88,4035.16) 3772.87,4051.15 3772.87,4165.15 v1(3896.88,4289.16)
  Bottom Layer w10: C45.1@3736.44,3985.16 3756.88,4005.6 v1(3756.88,4035.16)
$3N22326: BUZZER.3 Q3.3 | length 75.6
  Top Layer w10: BUZZER.3@4119.58,3883.15 4156.87,3883.15 v1(4158.88,3885.16)
  Bottom Layer w10: v1(4158.88,3885.16) 4191.51,3885.16 Q3.3@4193.51,3883.16
$3N22330: Q3.1 R26.2 | length 83.4
  Bottom Layer w10: Q3.1@4272.25,3920.56 4273.99,3918.82 R26.2@4354.88,3918.82
$3N25090:  | length 126.9
  Inner1 w10: v2(3774.88,3194.46) 3852.66,3272.24 v2(3852.66,3289.15)
$3N25501: Q1.3 U34.10 | length 405.3
  Inner1 w20: v1(4645.9,3357.16) 4642.88,3354.15 4642.88,3195.16 v1(4720.88,3117.16)
  Bottom Layer w10: Q1.3@4626.25,3399.16 4645.9,3379.52 v1(4645.9,3357.16)
  Bottom Layer w20: v1(4720.88,3117.16) 4722.29,3115.76 U34.10@4801.88,3115.76
$3N25503: Q1.1 R24.2 | length 61.2
  Bottom Layer w10: R24.2@4486.54,3361.16 4546.91,3361.16 Q1.1@4547.51,3361.76
$3N26223: Q2.1 R25.2 | length 121.1
  Bottom Layer w10: Q2.1@3430.25,3504.56 3430.25,3484.56 3462.25,3452.56 3486.6,3452.56 3486.68,3452.64 3486.68,3472.49 R25.2@3478.53,3480.64
$3N26229: Q2.3 U33.1 | length 596.9
  Inner1 w10: v1(3218.88,3051.16) 3218.88,3364.53 v1(3341.51,3487.16)
  Bottom Layer w10: U33.1@3176.88,3115.76 3176.88,3093.16 v1(3218.88,3051.16) ; v1(3341.51,3487.16) 3351.51,3477.16 Q2.3@3351.51,3463.16
$3N29548: C47.2 U45.1 | length 386.4
  Top Layer w10: v2(3834.52,3812.68) 3840.74,3812.68 v2(4048.88,3604.54)
  Bottom Layer w10: C47.2@3833.3,3774.09 3834.52,3775.31 v2(3834.52,3812.68) ; U45.1@4013.9,3576.16 4020.51,3576.16 v2(4048.88,3604.54)
$3N29821: U17.2 U46.5 | length 3056.4
  Inner1 w10: v1(3351.88,6318.16) 3450.67,6219.38 3450.67,5578.83 4131.42,4898.09 4131.42,3715.69 v1(4122.88,3707.16)
  Bottom Layer w10: v1(3351.88,6318.16) 3364.62,6318.16 U17.2@3388.91,6293.87 ; U46.5@4053.65,3700.82 4116.54,3700.82 v1(4122.88,3707.16)
$3N29823: U18.1 U46.1 | length 4175.9
  Inner1 w10: v1(3848.88,6463.16) 3848.88,6443.16 3840.88,6435.16 3820.88,6455.16 3650.67,6455.16 3607.68,6412.18 3357.9,6412.18 3167.62,6221.9 3119.13,6221.91 3048.88,6151.66 3048.88,4503.16 3638.88,3913.16 3988.88,3913.16 4013.88,3888.16 v1(4041.88,3888.16)
  Bottom Layer w10: U18.1@3837.43,6417.16 3846.88,6417.16 3870.88,6441.16 v1(3848.88,6463.16) ; U46.1@3947.7,3703.76 3952.7,3698.76 3958.4,3698.76 3981.4,3721.77 3981.4,3754.93 4023.83,3797.36 4035.77,3797.36 4046.88,3808.47 4046.88,3883.16 v1(4041.88,3888.16)
$3N29825: U16.2 U47.5 | length 4029.1
  Inner1 w10: v1(3354.88,6465.16) 3352.88,6467.16 3326.88,6467.16 3239.05,6379.33 3239.05,6356.83 3150.13,6267.91 3144.13,6267.91 3030.87,6154.65 3030.87,4336.11 3467.83,3899.15 3856.9,3899.15 4226.88,3529.16 4234.88,3529.16 4238.88,3525.16 v1(4238.88,3503.16)
  Bottom Layer w10: v1(3354.88,6465.16) 3388.33,6431.71 U16.2@3388.33,6417.16 ; v1(4238.88,3503.16) 4285.47,3503.16 U47.5@4334.07,3551.76
$3N29827: U19.1 U47.1 | length 3226.4
  Inner3 w10: v1(3766.88,6277.16) 3766.88,6088.98 3566.88,5888.98 3566.88,4267.16 4104.88,3729.16 4133.4,3729.16 4145.88,3716.68 4145.88,3682.17 v1(4268.88,3559.16)
  Bottom Layer w10: v1(3766.88,6277.16) 3833.43,6277.16 U19.1@3841.43,6285.16 ; U47.1@4231.7,3551.76 4261.48,3551.76 v1(4268.88,3559.16)
$3N29841: C47.1 U45.2 | length 476.1
  Inner1 w10: v2(3780.96,3809.84) 3780.96,3690.96 3928.1,3543.83 3934.09,3543.83 3947.56,3530.36 3947.56,3524.36 v2(3964.56,3507.37)
  Bottom Layer w10: C47.1@3778.18,3774.09 3780.96,3776.87 v2(3780.96,3809.84) ; v2(3964.56,3507.37) 3995.11,3507.37 U45.2@4013.9,3526.16
$3N29881: R27.1 R28.1 U45.5 | length 95.8
  Bottom Layer w10: R27.1@3793.92,3331.16 3795.92,3333.16 R28.1@3795.92,3383.16 ; R28.1@3795.92,3383.16 U45.5@3795.86,3426.16
$5N714: R3.2 U1.66 | length 628.1
  Top Layer w9: U1.66@3895.38,5989.89 3895.38,5989.28 3907.54,5977.11 3907.54,5952.77 v1(3898.2,5943.42)
  Top Layer w10: R3.2@3464.54,5613.16 3465.04,5612.66 v1(3508.4,5612.66)
  Inner1 w10: v1(3508.4,5612.66) 3598.87,5703.13 3598.87,5703.48 3683.55,5788.17 3683.91,5788.17 3843.16,5947.42 v1@3898.2,5947.42
$5N753: R4.2 U1.67 | length 750.6
  Top Layer w9: v1(3855.48,5995.95) 3867.05,5995.95 U1.67@3884.24,5978.76
  Top Layer w10: R4.2@3464.54,5553.16 v1(3508.86,5553.16)
  Inner1 w10: v1(3508.86,5553.16) 3464.69,5597.33 3464.69,5686.22 3774.42,5995.95 v1(3855.48,5995.95)
$5N865: R12.1 USB1.4 | length 114.1
  Top Layer w10: v1(3234.83,5633.16) 3266.18,5633.16 3266.98,5632.37 USB1.4@3290.39,5632.37
  Bottom Layer w10: R12.1@3178.25,5629.16 3182.25,5633.16 v1(3234.83,5633.16)
$5N907: R13.1 USB1.10 | length 113.1
  Top Layer w10: v1(3234.83,5513.84) 3289.97,5513.84 USB1.10@3290.39,5514.26
  Bottom Layer w10: R13.1@3175.93,5514.25 3231.79,5514.25 v1@3232.88,5513.16
$5N1500: L3.1 U1.63 | length 1905.4
  Top Layer w9: U1.63@3928.78,6021.3 3946.88,6003.19 v1@3946.88,5993.16
  Inner1 w10: v1(3946.88,5995.16) 3946.88,5840.84 3825.9,5719.85 3825.9,5648.88 3807.88,5630.86 3807.88,5591.99 4338.88,5060.98 v1(4338.88,4769.16)
  Bottom Layer w10: L3.1@4131.31,4554.98 4131.31,4674.42 4170.99,4714.11 4283.83,4714.11 v1(4338.88,4769.16)
$5N1577: C32.1 R14.2 U1.61 | length 1917.2
  Top Layer w10: U1.61@3951.05,6045.57 3961.48,6035.15 3972.88,6035.15 v1(3981.88,6026.14)
  Bottom Layer w10: v1(3981.88,6026.14) 3994.12,6026.14 4012.38,6007.87 ; R14.2@4012.38,6115.91 4012.38,6007.87 ; C32.1@4545.58,4575.16 4460.43,4660.31 4460.43,4709.72 3986.88,5183.27 3986.88,5549.2 4081.87,5644.19 4081.87,5672.2 4012.38,5741.69 4012.38,6007.87
$5N3555: R15.2 U1.35 | length 1371.8
  Top Layer w10: v1(4134.88,5739.16) 4145.11,5739.16 U1.35@4167.62,5716.65 ; R15.2@4254.25,5095.89 4254.25,5230.53 v1(4266.88,5243.16)
  Inner1 w10: v1(4134.88,5739.16) 4278.56,5739.16 4485.87,5531.85 4485.87,5514.47 4473.58,5502.18 4456.19,5502.18 4341.02,5617.35 4266.88,5617.35 4266.88,5518.84 4359.87,5425.85 4359.87,5408.47 4266.88,5315.48 v1(4266.88,5243.16)
$5N4153: D4.1 LED-RUN.1 | length 83.4
  Top Layer w10: LED-RUN.1@4407.6,4889.77 4408.28,4889.08 v1(4454.88,4889.08)
  Bottom Layer w10: v1(4454.88,4889.08) D4.1@4490.69,4889.08
$5N4199: D3.1 LED-QSPI_SS.1 | length 157.4
  Top Layer w10: LED-QSPI_SS.1@3589.9,4882.49 3589.9,4888.3 3653.46,4951.86 D3.1@3653.46,5013.57
$5N4367: D5.1 LED6.1 | length 324.8
  Top Layer w10: v1(4350.88,4189.16) 4370.08,4208.36 v1(4370.08,4240.09)
  Bottom Layer w10: D5.1@4197.61,4103.99 4265.71,4103.99 v1(4350.88,4189.16) ; LED6.1@4312.23,4287.16 4323.01,4287.16 v1(4370.08,4240.09)
$5N4916: C34.2 R17.2 U6.1 | length 206.8
  Bottom Layer w10: R17.2@4424,5858.9 4424.19,5859.09 U6.1@4424.19,5947.7 4425.13,5948.63 4495.32,5878.44 C34.2@4495.32,5861.16
$5N10092: QSPI_SS.3 R16.1 | length 74.5
  Top Layer w10: R16.1@3177.22,5021.16 3179.72,5023.66 QSPI_SS.3@3179.72,5094.58
$5N10100: D3.2 QSPI_SS.4 | length 88.1
  Top Layer w10: D3.2@3516.85,5013.57 3534.05,5030.76 QSPI_SS.4@3534.05,5094.58
$5N12881: R15.1 RUN.3 | length 131.7
  Top Layer w10: R15.1@4313.57,5095.89 4443.41,5095.89 RUN.3@4444.72,5094.58
$5N12933: D4.2 RUN.4 | length 288.3
  Top Layer w10: v1(4629.63,4945.1) 4649.57,4945.1 RUN.4@4799.05,5094.58
  Bottom Layer w10: D4.2@4627.3,4889.08 4629.63,4891.41 v1(4629.63,4945.1)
